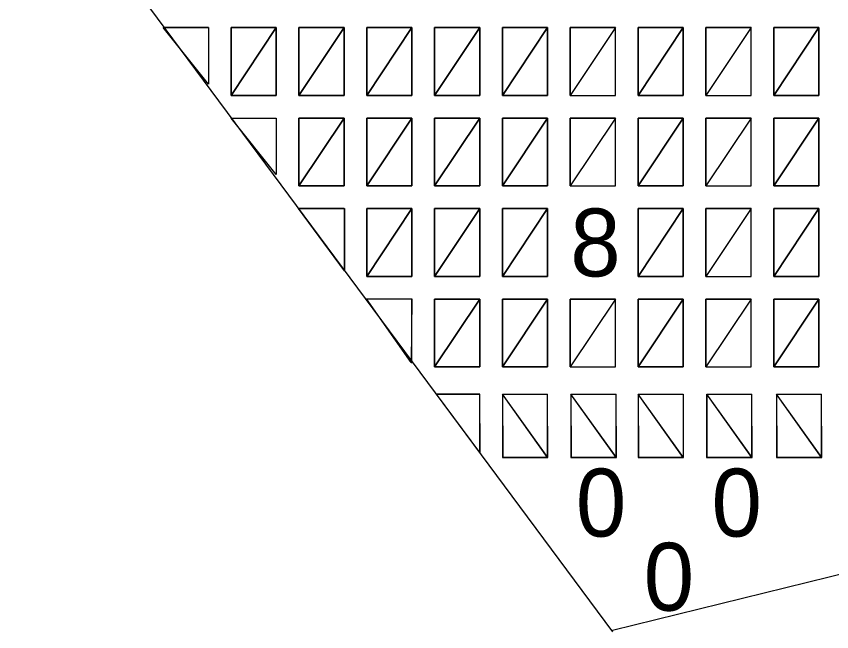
# Model space of a CAD drawing. Extents: x -10 to 89.7, y -4.8 to 22.
# Drawn here: x 2.2987 to 2.5039, y 1.4463 to 1.6012 of the extents above; entities that cross this region are included whole.
import ezdxf

# ---------------------------------------------------------------- set-up
doc = ezdxf.new("R2010")
doc.units = 0
doc.layers.add('Default', color=7, linetype='Continuous')

msp = doc.modelspace()

# ---------------------------------------------------------------- linework, layer by layer
at = {"layer": 'Default'}
for p, q in [((2.28859, 1.66215), (2.44873, 1.44635)), ((2.34706, 1.59832), (2.33568, 1.59832)), ((2.34706, 1.59832), (2.34706, 1.58409)), ((2.36413, 1.59832), (2.35275, 1.59832)), ((2.35275, 1.59832), (2.35275, 1.58125)), ((2.36413, 1.58125), (2.36413, 1.59832)), ((2.36983, 1.59832), (2.36983, 1.58125)), ((2.38121, 1.59832), (2.36983, 1.59832)), ((2.38121, 1.58125), (2.38121, 1.59832)), ((2.39828, 1.59832), (2.3869, 1.59832)), ((2.3869, 1.59832), (2.3869, 1.58125)), ((2.39828, 1.58125), (2.39828, 1.59832)), ((2.40397, 1.59832), (2.40397, 1.58125)), ((2.41535, 1.59832), (2.40397, 1.59832)), ((2.41535, 1.58125), (2.41535, 1.59832)), ((2.43242, 1.59832), (2.42104, 1.59832)), ((2.42104, 1.59832), (2.42104, 1.58125)), ((2.43242, 1.58125), (2.43242, 1.59832)), ((2.43811, 1.59832), (2.43811, 1.58125)), ((2.44949, 1.59832), (2.43811, 1.59832)), ((2.44949, 1.58125), (2.44949, 1.59832)), ((2.46656, 1.59832), (2.45518, 1.59832)), ((2.45518, 1.59832), (2.45518, 1.58125)), ((2.46656, 1.58125), (2.46656, 1.59832)), ((2.47225, 1.59832), (2.47225, 1.58125)), ((2.48363, 1.59832), (2.47225, 1.59832)), ((2.48363, 1.58125), (2.48363, 1.59832)), ((2.48932, 1.59832), (2.48932, 1.58125)), ((2.5007, 1.59832), (2.48932, 1.59832)), ((2.5007, 1.58125), (2.5007, 1.59832)), ((2.35275, 1.58125), (2.36413, 1.58125)), ((2.36983, 1.58125), (2.38121, 1.58125)), ((2.3869, 1.58125), (2.39828, 1.58125)), ((2.40397, 1.58125), (2.41535, 1.58125)), ((2.42104, 1.58125), (2.43242, 1.58125)), ((2.43811, 1.58125), (2.44949, 1.58125)), ((2.45518, 1.58125), (2.46656, 1.58125)), ((2.47225, 1.58125), (2.48363, 1.58125)), ((2.48932, 1.58125), (2.5007, 1.58125)), ((2.35275, 1.57556), (2.36413, 1.57556)), ((2.36413, 1.57556), (2.36413, 1.56133)), ((2.38121, 1.57556), (2.36983, 1.57556)), ((2.36983, 1.57556), (2.36983, 1.55848)), ((2.38121, 1.55848), (2.38121, 1.57556)), ((2.3869, 1.57556), (2.3869, 1.55848)), ((2.39828, 1.57556), (2.3869, 1.57556)), ((2.39828, 1.55848), (2.39828, 1.57556)), ((2.41535, 1.57556), (2.40397, 1.57556)), ((2.40397, 1.57556), (2.40397, 1.55848)), ((2.41535, 1.55848), (2.41535, 1.57556)), ((2.42104, 1.57556), (2.42104, 1.55848)), ((2.43242, 1.57556), (2.42104, 1.57556)), ((2.43242, 1.55848), (2.43242, 1.57556)), ((2.44949, 1.57556), (2.43811, 1.57556)), ((2.43811, 1.57556), (2.43811, 1.55848)), ((2.44949, 1.55848), (2.44949, 1.57556)), ((2.45518, 1.57556), (2.45518, 1.55848)), ((2.46656, 1.57556), (2.45518, 1.57556)), ((2.46656, 1.55848), (2.46656, 1.57556)), ((2.48363, 1.57556), (2.47225, 1.57556)), ((2.47225, 1.57556), (2.47225, 1.55848)), ((2.48363, 1.55848), (2.48363, 1.57556)), ((2.5007, 1.57556), (2.48932, 1.57556)), ((2.48932, 1.57556), (2.48932, 1.55848)), ((2.5007, 1.55848), (2.5007, 1.57556)), ((2.36983, 1.55848), (2.38121, 1.55848)), ((2.3869, 1.55848), (2.39828, 1.55848)), ((2.40397, 1.55848), (2.41535, 1.55848)), ((2.42104, 1.55848), (2.43242, 1.55848)), ((2.43811, 1.55848), (2.44949, 1.55848)), ((2.45518, 1.55848), (2.46656, 1.55848)), ((2.47225, 1.55848), (2.48363, 1.55848)), ((2.48932, 1.55848), (2.5007, 1.55848)), ((2.38121, 1.55279), (2.36968, 1.55279)), ((2.38121, 1.55279), (2.38121, 1.53745)), ((2.39828, 1.55279), (2.3869, 1.55279)), ((2.3869, 1.55279), (2.3869, 1.53572)), ((2.39828, 1.53572), (2.39828, 1.55279)), ((2.40397, 1.55279), (2.40397, 1.53572)), ((2.41535, 1.55279), (2.40397, 1.55279)), ((2.41535, 1.53572), (2.41535, 1.55279)), ((2.43242, 1.55279), (2.42104, 1.55279)), ((2.42104, 1.55279), (2.42104, 1.53572)), ((2.43242, 1.53572), (2.43242, 1.55279)), ((2.46656, 1.55279), (2.45518, 1.55279)), ((2.45518, 1.55279), (2.45518, 1.53572)), ((2.46656, 1.53572), (2.46656, 1.55279)), ((2.47225, 1.55279), (2.47225, 1.53572)), ((2.48363, 1.55279), (2.47225, 1.55279)), ((2.48363, 1.53572), (2.48363, 1.55279)), ((2.48932, 1.55279), (2.48932, 1.53572)), ((2.5007, 1.55279), (2.48932, 1.55279)), ((2.5007, 1.53572), (2.5007, 1.55279)), ((2.3869, 1.53572), (2.39828, 1.53572)), ((2.40397, 1.53572), (2.41535, 1.53572)), ((2.42104, 1.53572), (2.43242, 1.53572)), ((2.45518, 1.53572), (2.46656, 1.53572)), ((2.47225, 1.53572), (2.48363, 1.53572)), ((2.48932, 1.53572), (2.5007, 1.53572)), ((2.39828, 1.53003), (2.3869, 1.53003)), ((2.39828, 1.51392), (2.39828, 1.53003)), ((2.41535, 1.53003), (2.40397, 1.53003)), ((2.40397, 1.53003), (2.40397, 1.51296)), ((2.41535, 1.51296), (2.41535, 1.53003)), ((2.42104, 1.53003), (2.42104, 1.51296)), ((2.43242, 1.53003), (2.42104, 1.53003)), ((2.43242, 1.51296), (2.43242, 1.53003)), ((2.44949, 1.53003), (2.43811, 1.53003)), ((2.43811, 1.53003), (2.43811, 1.51296)), ((2.44949, 1.51296), (2.44949, 1.53003)), ((2.45518, 1.53003), (2.45518, 1.51296)), ((2.46656, 1.53003), (2.45518, 1.53003)), ((2.46656, 1.51296), (2.46656, 1.53003)), ((2.48363, 1.53003), (2.47225, 1.53003)), ((2.47225, 1.53003), (2.47225, 1.51296)), ((2.48363, 1.51296), (2.48363, 1.53003)), ((2.5007, 1.53003), (2.48932, 1.53003)), ((2.48932, 1.53003), (2.48932, 1.51296)), ((2.5007, 1.51296), (2.5007, 1.53003)), ((2.40397, 1.51296), (2.41535, 1.51296)), ((2.42104, 1.51296), (2.43242, 1.51296)), ((2.43811, 1.51296), (2.44949, 1.51296)), ((2.45518, 1.51296), (2.46656, 1.51296)), ((2.47225, 1.51296), (2.48363, 1.51296)), ((2.48932, 1.51296), (2.5007, 1.51296)), ((2.70953, 1.5109), (2.44872, 1.44664)), ((2.41537, 1.50611), (2.4045, 1.50611)), ((2.41535, 1.49131), (2.41535, 1.50611)), ((2.42104, 1.50611), (2.42104, 1.4902)), ((2.42105, 1.50611), (2.43241, 1.50611)), ((2.43242, 1.4902), (2.43242, 1.50611)), ((2.43828, 1.50611), (2.43828, 1.4902)), ((2.43829, 1.50611), (2.44965, 1.50611)), ((2.44966, 1.4902), (2.44966, 1.50611)), ((2.4552, 1.50611), (2.4552, 1.4902)), ((2.45521, 1.50611), (2.46657, 1.50611)), ((2.46658, 1.4902), (2.46658, 1.50611)), ((2.47244, 1.50611), (2.47244, 1.4902)), ((2.47246, 1.50611), (2.48382, 1.50611)), ((2.48382, 1.4902), (2.48382, 1.50611)), ((2.49001, 1.50611), (2.49001, 1.4902)), ((2.49002, 1.50611), (2.50138, 1.50611)), ((2.50139, 1.4902), (2.50139, 1.50611)), ((2.42104, 1.4902), (2.43242, 1.4902)), ((2.43828, 1.4902), (2.44966, 1.4902)), ((2.4552, 1.4902), (2.46658, 1.4902)), ((2.47244, 1.4902), (2.48382, 1.4902)), ((2.49001, 1.4902), (2.50139, 1.4902))]:
    msp.add_line(p, q, dxfattribs=at)
for points in [[(2.33568, 1.59832), (2.34706, 1.59832), (2.34706, 1.58409)], [(2.34706, 1.59832), (2.34706, 1.59832), (2.34706, 1.59832)], [(2.36413, 1.59832), (2.36413, 1.58125), (2.35275, 1.58125)], [(2.35275, 1.58125), (2.35275, 1.59832), (2.36413, 1.59832)], [(2.36413, 1.59832), (2.36413, 1.59832), (2.36413, 1.59832)], [(2.36983, 1.58125), (2.36983, 1.59832), (2.38121, 1.59832)], [(2.38121, 1.59832), (2.38121, 1.58125), (2.36983, 1.58125)], [(2.38121, 1.59832), (2.38121, 1.59832), (2.38121, 1.59832)], [(2.39828, 1.59832), (2.39828, 1.58125), (2.3869, 1.58125)], [(2.3869, 1.58125), (2.3869, 1.59832), (2.39828, 1.59832)], [(2.39828, 1.59832), (2.39828, 1.59832), (2.39828, 1.59832)], [(2.41535, 1.59832), (2.41535, 1.58125), (2.40397, 1.58125)], [(2.40397, 1.58125), (2.40397, 1.59832), (2.41535, 1.59832)], [(2.42104, 1.58125), (2.42104, 1.59832), (2.43242, 1.59832)], [(2.43242, 1.59832), (2.43242, 1.58125), (2.42104, 1.58125)], [(2.43811, 1.58125), (2.43811, 1.59832), (2.44949, 1.59832)], [(2.43811, 1.58125), (2.44949, 1.58125), (2.44949, 1.59832)], [(2.45518, 1.58125), (2.45518, 1.59832), (2.46656, 1.59832)], [(2.46656, 1.59832), (2.46656, 1.58125), (2.45518, 1.58125)], [(2.47225, 1.58125), (2.47225, 1.59832), (2.48363, 1.59832)], [(2.47225, 1.58125), (2.48363, 1.58125), (2.48363, 1.59832)], [(2.5007, 1.59832), (2.5007, 1.58125), (2.48932, 1.58125)], [(2.48932, 1.58125), (2.48932, 1.59832), (2.5007, 1.59832)], [(2.35275, 1.57556), (2.36413, 1.57556), (2.36413, 1.56133)], [(2.38121, 1.57556), (2.38121, 1.55848), (2.36983, 1.55848)], [(2.36983, 1.55848), (2.36983, 1.57556), (2.38121, 1.57556)], [(2.38121, 1.57556), (2.38121, 1.57556), (2.38121, 1.57556)], [(2.3869, 1.55848), (2.3869, 1.57556), (2.39828, 1.57556)], [(2.39828, 1.57556), (2.39828, 1.55848), (2.3869, 1.55848)], [(2.39828, 1.57556), (2.39828, 1.57556), (2.39828, 1.57556)], [(2.40397, 1.55848), (2.40397, 1.57556), (2.41535, 1.57556)], [(2.41535, 1.57556), (2.41535, 1.55848), (2.40397, 1.55848)], [(2.43242, 1.57556), (2.43242, 1.55848), (2.42104, 1.55848)], [(2.42104, 1.55848), (2.42104, 1.57556), (2.43242, 1.57556)], [(2.43811, 1.55848), (2.44949, 1.55848), (2.44949, 1.57556)], [(2.43811, 1.55848), (2.43811, 1.57556), (2.44949, 1.57556)], [(2.46656, 1.57556), (2.46656, 1.55848), (2.45518, 1.55848)], [(2.45518, 1.55848), (2.45518, 1.57556), (2.46656, 1.57556)], [(2.47225, 1.55848), (2.48363, 1.55848), (2.48363, 1.57556)], [(2.47225, 1.55848), (2.47225, 1.57556), (2.48363, 1.57556)], [(2.48932, 1.55848), (2.48932, 1.57556), (2.5007, 1.57556)], [(2.5007, 1.57556), (2.5007, 1.55848), (2.48932, 1.55848)], [(2.38126, 1.53713), (2.36968, 1.55283), (2.38126, 1.55283)], [(2.39828, 1.55279), (2.39828, 1.53572), (2.3869, 1.53572)], [(2.3869, 1.53572), (2.3869, 1.55279), (2.39828, 1.55279)], [(2.39828, 1.55279), (2.39828, 1.55279), (2.39828, 1.55279)], [(2.41535, 1.55279), (2.41535, 1.53572), (2.40397, 1.53572)], [(2.40397, 1.53572), (2.40397, 1.55279), (2.41535, 1.55279)], [(2.42104, 1.53572), (2.42104, 1.55279), (2.43242, 1.55279)], [(2.43242, 1.55279), (2.43242, 1.53572), (2.42104, 1.53572)], [(2.45518, 1.53572), (2.45518, 1.55279), (2.46656, 1.55279)], [(2.46656, 1.55279), (2.46656, 1.53572), (2.45518, 1.53572)], [(2.47225, 1.53572), (2.47225, 1.55279), (2.48363, 1.55279)], [(2.47225, 1.53572), (2.48363, 1.53572), (2.48363, 1.55279)], [(2.5007, 1.55279), (2.5007, 1.53572), (2.48932, 1.53572)], [(2.48932, 1.53572), (2.48932, 1.55279), (2.5007, 1.55279)], [(2.39804, 1.51404), (2.38685, 1.53007), (2.39823, 1.53007)], [(2.40397, 1.51296), (2.40397, 1.53003), (2.41535, 1.53003)], [(2.41535, 1.53003), (2.41535, 1.51296), (2.40397, 1.51296)], [(2.43242, 1.53003), (2.43242, 1.51296), (2.42104, 1.51296)], [(2.42104, 1.51296), (2.42104, 1.53003), (2.43242, 1.53003)], [(2.43811, 1.51296), (2.44949, 1.51296), (2.44949, 1.53003)], [(2.43811, 1.51296), (2.43811, 1.53003), (2.44949, 1.53003)], [(2.46656, 1.53003), (2.46656, 1.51296), (2.45518, 1.51296)], [(2.45518, 1.51296), (2.45518, 1.53003), (2.46656, 1.53003)], [(2.47225, 1.51296), (2.48363, 1.51296), (2.48363, 1.53003)], [(2.47225, 1.51296), (2.47225, 1.53003), (2.48363, 1.53003)], [(2.48932, 1.51296), (2.48932, 1.53003), (2.5007, 1.53003)], [(2.5007, 1.53003), (2.5007, 1.51296), (2.48932, 1.51296)], [(2.40443, 1.50611), (2.4153, 1.50611), (2.41537, 1.49143)], [(2.42112, 1.49026), (2.43248, 1.49015), (2.42105, 1.50611)], [(2.42105, 1.50611), (2.43234, 1.50611), (2.43241, 1.49015)], [(2.43829, 1.50611), (2.44958, 1.50611), (2.44965, 1.49015)], [(2.43836, 1.49026), (2.44972, 1.49015), (2.43829, 1.50611)], [(2.45521, 1.50611), (2.4665, 1.50611), (2.46657, 1.49015)], [(2.45528, 1.49026), (2.46664, 1.49015), (2.45521, 1.50611)], [(2.47253, 1.49026), (2.48389, 1.49015), (2.47246, 1.50611)], [(2.47246, 1.50611), (2.48375, 1.50611), (2.48382, 1.49015)], [(2.49009, 1.49026), (2.50145, 1.49015), (2.49002, 1.50611)], [(2.49002, 1.50611), (2.50131, 1.50611), (2.50138, 1.49015)], [(2.43241, 1.49015), (2.43241, 1.49015), (2.43248, 1.49015), (2.42112, 1.49026)], [(2.44965, 1.49015), (2.44965, 1.49015), (2.44972, 1.49015), (2.43836, 1.49026)], [(2.46657, 1.49015), (2.46657, 1.49015), (2.46664, 1.49015), (2.45528, 1.49026)], [(2.48382, 1.49015), (2.48382, 1.49015), (2.48389, 1.49015), (2.47253, 1.49026)], [(2.50138, 1.49015), (2.50138, 1.49015), (2.50145, 1.49015), (2.49009, 1.49026)]]:
    msp.add_lwpolyline(points, close=True, dxfattribs=at)

# ---------------------------------------------------------------- texts
for s, p in [('8', (2.43811, 1.53572)), ('0', (2.43953, 1.47028)), ('0', (2.47367, 1.47028)), ('0', (2.4566, 1.45164))]:
    msp.add_text(s, height=0.01707, dxfattribs=at).set_placement(p)

doc.saveas('drawing.dxf')
